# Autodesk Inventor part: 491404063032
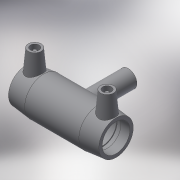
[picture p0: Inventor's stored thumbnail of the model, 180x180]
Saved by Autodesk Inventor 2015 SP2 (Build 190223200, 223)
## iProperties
Created: 2017-06
Part Number: 491404063032
Material: Generic
Description: PLASSON REDUCING TEE 63x32x63
Document SubType Name: Modeling
Designer: KIM
Mass: 57.3761 g
Surface Area: 241.06 cm^2
Volume: 57.3761 cm^3
Density: 1 g/cm^3
Appearance: Default
Author: KIM
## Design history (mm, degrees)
derived "491404.ipt"
feature "Solid1::491404.ipt"
tag "TaggingFeature1"
body "Solid1"
other parameters: "d0" = 167, "d1" = 63, "d2" = 82, "d3" = 58, "d4" = 33.4, "d5" = 73.8, "d6" = 59.85, "d7" = 63, "d8" = 168 deg, "d10" = 23.2, "d11" = 7.73333, "d13" = 167, "d14" = 17.6296, "d17" = 56.7, "d18" = 63, "d19" = 3.52592, "d20" = 168 deg, "d22" = 76.26, "d23" = 82, "d25" = 135 deg, "d26" = 116.9, "d29" = 58, "d30" = 15, "d31" = 66.8, "d34" = 5 deg, "d35" = 15, "d39" = 5 deg, "d41" = 4, "d42" = 14, "d43" = 0, "d45" = 4, "d46" = 6, "d47" = 0, "d48" = -93, "d49" = 32, "d51" = 0, "d52" = 25.6, "d54" = 0, "d55" = 73.8, "d56" = 82, "d57" = 58.45, "d58" = 135 deg, "d59" = 58, "d60" = 58, "d61" = 135 deg, "d62" = 93, "d72" = 75.985, "d73" = 37.9925, "d74" = -93, "d75" = 33.6, "d77" = 0, "d78" = 25.6, "d80" = 0, "d81" = 32, "d82" = 52, "d83" = 0, "d84" = 3, "d85" = 0, "d86" = 19.33333, "d87" = 74.7348, "d88" = 7.73333, "d89" = 3, "d90" = 0, "d_" = 63, "L_" = 167, "L_1" = 58, "D_" = 82, "A_" = 58, "d_2" = 12, "H_" = 93, "d_1" = 32
